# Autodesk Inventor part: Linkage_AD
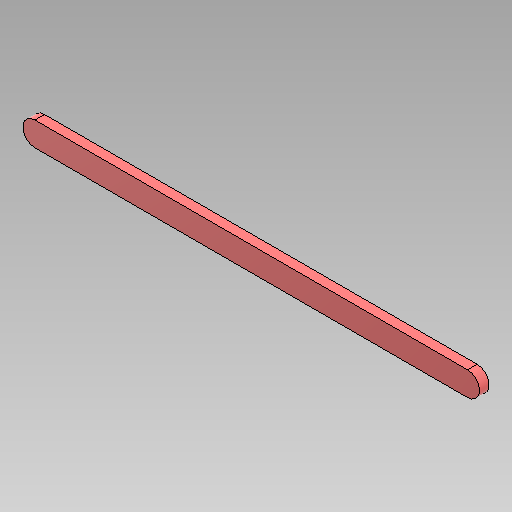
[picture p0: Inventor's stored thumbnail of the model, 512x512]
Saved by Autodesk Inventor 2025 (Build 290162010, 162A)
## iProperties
Created: 2024-10
Part Number: Linkage_AD
Material: Generic
Document SubType Name: Modeling
Designer: Dennis
Density: 1 g/cm^3
Appearance: Smooth - Red
Mass: 0.93927 g
Surface Area: 13.3069 cm^2
Volume: 0.93927 cm^3
Author: Dennis
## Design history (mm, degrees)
sketch "Sketch1"
  geometry: L1 (0, 0)-(90, 0); L2 (0, -2.5)-(90, -2.5); L3 (90, 2.5)-(0, 2.5); A1 r 2.5 centre (0, 0) between (0, 2.5) and (0, -2.5); A2 r 2.5 centre (90, 0) between (90, -2.5) and (90, 2.5); 1 further point
  constraints: 8 end point, 4 point on circle, 4 tangent, 2 centre point, 1 horizontal, 1 midpoint, 1 parallel
  dimensions: "d0" = 5 distance between parallel lines of L2 L3 (= w_); "d1" = 90 distance of L1.start L1.end (= AD_)
extrude "Extrusion1" new body sketch "Sketch1" stored distance "d2" = 2 (= t_); taper "d3" = 0 deg
body "Solid1"
other parameters: "AD_" = 90 [user parameter; used in 1 equation term], "w_" = 5 [user parameter; used in 1 equation term], "t_" = 2 [user parameter; used in 1 equation term]
